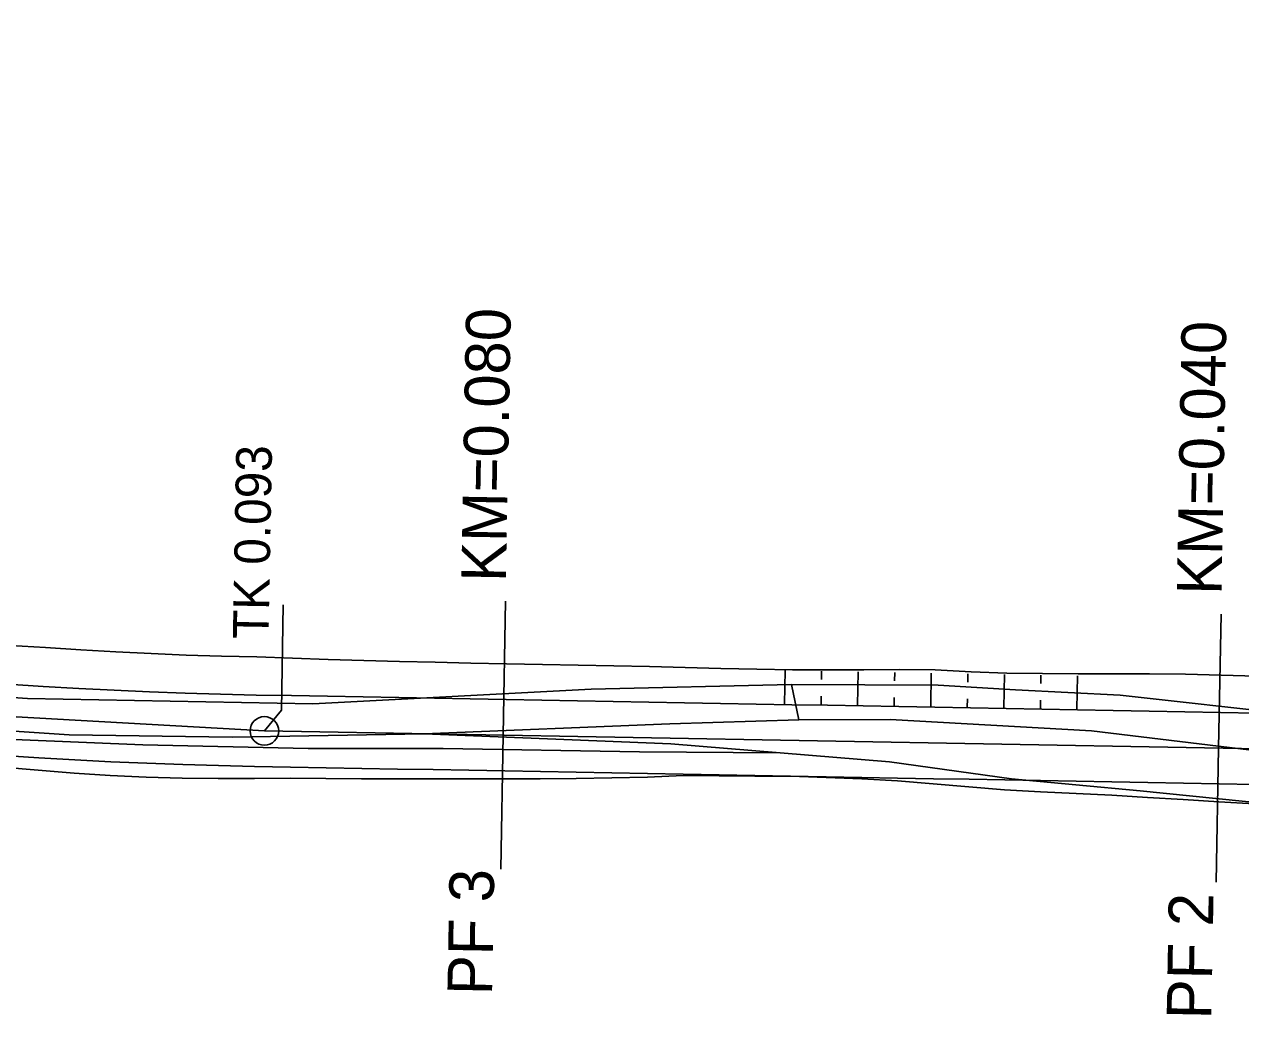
# Model space of a CAD drawing. Extents: x -478000 to -474772, y -1116940 to -1114124.
# Drawn here: x -477364.4 to -477296.3, y -1116626.8 to -1116571.3 of the extents above; entities that cross this region are included whole.
import ezdxf

# ---------------------------------------------------------------- set-up
doc = ezdxf.new("R2010")
doc.units = 0
for name, color, linetype in [('hrana_P', 7, 'Continuous'), ('L', 7, 'Continuous'), ('P', 7, 'Continuous'), ('POLYGONY_SITUACE_PF', 7, 'Continuous'), ('POLYGONY_SITUACE_PF_POPISY', 7, 'Continuous'), ('POLYGONY_SITUACE_PO', 7, 'Continuous')]:
    doc.layers.add(name, color=color, linetype=linetype)

msp = doc.modelspace()

# ---------------------------------------------------------------- linework, layer by layer
for points in [[(-477349.986, -1116609.731), (-477349.879, -1116603.837)], [(-477349.986, -1116609.731), (-477350.936, -1116610.9)]]:
    msp.add_lwpolyline(points)
at = {"layer": 'hrana_P'}
for p, q in [((-477365.605, -1116612.924), (-477363.595, -1116613.102)), ((-477363.595, -1116613.102), (-477361.582, -1116613.26)), ((-477361.582, -1116613.26), (-477359.568, -1116613.395)), ((-477359.568, -1116613.395), (-477357.552, -1116613.494)), ((-477357.552, -1116613.494), (-477355.534, -1116613.551)), ((-477355.534, -1116613.551), (-477353.516, -1116613.568)), ((-477353.516, -1116613.568), (-477351.497, -1116613.571)), ((-477351.497, -1116613.571), (-477349.492, -1116613.549)), ((-477349.492, -1116613.549), (-477347.492, -1116613.566)), ((-477347.492, -1116613.566), (-477345.492, -1116613.586)), ((-477345.492, -1116613.586), (-477343.492, -1116613.587)), ((-477343.492, -1116613.587), (-477341.491, -1116613.593)), ((-477341.491, -1116613.593), (-477339.491, -1116613.59)), ((-477339.491, -1116613.59), (-477337.491, -1116613.592)), ((-477337.491, -1116613.592), (-477335.49, -1116613.582)), ((-477335.49, -1116613.582), (-477333.49, -1116613.559)), ((-477333.49, -1116613.559), (-477331.489, -1116613.534)), ((-477331.489, -1116613.534), (-477329.488, -1116613.485)), ((-477329.488, -1116613.485), (-477327.486, -1116613.403)), ((-477327.486, -1116613.403), (-477325.486, -1116613.423)), ((-477325.486, -1116613.423), (-477323.486, -1116613.435)), ((-477323.486, -1116613.435), (-477321.485, -1116613.44)), ((-477321.485, -1116613.44), (-477319.486, -1116613.505)), ((-477319.486, -1116613.505), (-477317.487, -1116613.586)), ((-477317.487, -1116613.586), (-477315.489, -1116613.704)), ((-477315.489, -1116613.704), (-477313.492, -1116613.86)), ((-477313.492, -1116613.86), (-477311.494, -1116614.029)), ((-477311.494, -1116614.029), (-477309.497, -1116614.208)), ((-477309.497, -1116614.208), (-477307.499, -1116614.305)), ((-477307.499, -1116614.305), (-477305.5, -1116614.406)), ((-477305.5, -1116614.406), (-477303.502, -1116614.507)), ((-477303.502, -1116614.507), (-477301.504, -1116614.623)), ((-477301.504, -1116614.623), (-477299.505, -1116614.744)), ((-477299.505, -1116614.744), (-477297.507, -1116614.866)), ((-477297.507, -1116614.866), (-477295.509, -1116614.987))]:
    msp.add_line(p, q, dxfattribs=at)
for points in [[(-477365.153, -1116606.116), (-477363.184, -1116606.225)], [(-477363.184, -1116606.225), (-477361.216, -1116606.356)], [(-477361.216, -1116606.356), (-477359.247, -1116606.474)], [(-477359.247, -1116606.474), (-477357.277, -1116606.572)], [(-477357.277, -1116606.572), (-477355.306, -1116606.656)], [(-477355.306, -1116606.656), (-477353.335, -1116606.714)], [(-477353.335, -1116606.714), (-477351.363, -1116606.761)], [(-477351.363, -1116606.761), (-477349.371, -1116606.83)], [(-477349.371, -1116606.83), (-477347.372, -1116606.894)], [(-477347.372, -1116606.894), (-477345.372, -1116606.955)], [(-477345.372, -1116606.955), (-477343.373, -1116607.007)], [(-477343.373, -1116607.007), (-477341.374, -1116607.059)], [(-477341.374, -1116607.059), (-477339.374, -1116607.102)], [(-477339.374, -1116607.102), (-477337.374, -1116607.142)], [(-477337.374, -1116607.142), (-477335.375, -1116607.182)], [(-477335.375, -1116607.182), (-477333.375, -1116607.216)], [(-477333.375, -1116607.216), (-477331.375, -1116607.249)], [(-477331.375, -1116607.249), (-477329.376, -1116607.295)], [(-477329.376, -1116607.295), (-477327.377, -1116607.353)], [(-477327.377, -1116607.353), (-477325.377, -1116607.403)], [(-477325.377, -1116607.403), (-477323.378, -1116607.449)], [(-477323.378, -1116607.449), (-477321.378, -1116607.491)], [(-477321.822, -1116609.379), (-477321.788, -1116607.52)], [(-477321.378, -1116607.491), (-477319.378, -1116607.485)], [(-477319.742, -1116607.558), (-477319.75, -1116608.022)], [(-477319.378, -1116607.485), (-477317.377, -1116607.477)], [(-477317.73, -1116609.454), (-477317.696, -1116607.595)], [(-477317.377, -1116607.477), (-477315.376, -1116607.458)], [(-477315.65, -1116607.633), (-477315.658, -1116608.098)], [(-477315.376, -1116607.458), (-477313.377, -1116607.48)], [(-477313.638, -1116609.53), (-477313.603, -1116607.671)], [(-477313.377, -1116607.48), (-477311.378, -1116607.596)], [(-477311.557, -1116607.709), (-477311.566, -1116608.173)], [(-477311.378, -1116607.596), (-477309.379, -1116607.673)], [(-477309.545, -1116609.605), (-477309.511, -1116607.746)], [(-477309.379, -1116607.673), (-477307.379, -1116607.687)], [(-477307.465, -1116607.784), (-477307.474, -1116608.249)], [(-477307.379, -1116607.687), (-477305.379, -1116607.697)], [(-477305.453, -1116609.681), (-477305.419, -1116607.822)], [(-477305.379, -1116607.697), (-477303.379, -1116607.701)], [(-477303.379, -1116607.701), (-477301.379, -1116607.704)], [(-477301.379, -1116607.704), (-477299.379, -1116607.723)], [(-477299.379, -1116607.723), (-477297.379, -1116607.777)], [(-477297.379, -1116607.777), (-477295.38, -1116607.831)], [(-477363.315, -1116608.417), (-477365.297, -1116608.292)], [(-477361.331, -1116608.529), (-477363.315, -1116608.417)], [(-477359.347, -1116608.628), (-477361.331, -1116608.529)], [(-477357.362, -1116608.714), (-477359.347, -1116608.628)], [(-477355.377, -1116608.786), (-477357.362, -1116608.714)], [(-477353.391, -1116608.845), (-477355.377, -1116608.786)], [(-477351.405, -1116608.891), (-477353.391, -1116608.845)], [(-477349.409, -1116608.927), (-477351.405, -1116608.891)], [(-477347.409, -1116608.964), (-477349.409, -1116608.927)], [(-477345.409, -1116609), (-477347.409, -1116608.964)], [(-477343.41, -1116609.036), (-477345.409, -1116609)], [(-477341.41, -1116609.072), (-477343.41, -1116609.036)], [(-477339.41, -1116609.108), (-477341.41, -1116609.072)], [(-477337.41, -1116609.144), (-477339.41, -1116609.108)], [(-477335.411, -1116609.18), (-477337.41, -1116609.144)], [(-477333.411, -1116609.216), (-477335.411, -1116609.18)], [(-477331.411, -1116609.252), (-477333.411, -1116609.216)], [(-477319.776, -1116609.417), (-477319.768, -1116608.952)], [(-477315.684, -1116609.492), (-477315.675, -1116609.027)], [(-477311.592, -1116609.568), (-477311.583, -1116609.103)], [(-477307.499, -1116609.643), (-477307.491, -1116609.178)], [(-477329.412, -1116609.288), (-477331.411, -1116609.252)], [(-477327.412, -1116609.324), (-477329.412, -1116609.288)], [(-477325.412, -1116609.36), (-477327.412, -1116609.324)], [(-477323.413, -1116609.396), (-477325.412, -1116609.36)], [(-477321.413, -1116609.433), (-477323.413, -1116609.396)], [(-477319.413, -1116609.469), (-477321.413, -1116609.433)], [(-477317.414, -1116609.505), (-477319.413, -1116609.469)], [(-477315.414, -1116609.541), (-477317.414, -1116609.505)], [(-477313.414, -1116609.577), (-477315.414, -1116609.541)], [(-477311.415, -1116609.613), (-477313.414, -1116609.577)], [(-477309.415, -1116609.649), (-477311.415, -1116609.613)], [(-477307.415, -1116609.685), (-477309.415, -1116609.649)], [(-477305.416, -1116609.721), (-477307.415, -1116609.685)], [(-477303.416, -1116609.757), (-477305.416, -1116609.721)], [(-477301.416, -1116609.793), (-477303.416, -1116609.757)], [(-477299.417, -1116609.829), (-477301.416, -1116609.793)], [(-477297.417, -1116609.866), (-477299.417, -1116609.829)], [(-477295.417, -1116609.902), (-477297.417, -1116609.866)], [(-477363.553, -1116612.41), (-477365.563, -1116612.283)], [(-477361.543, -1116612.524), (-477363.553, -1116612.41)], [(-477359.532, -1116612.624), (-477361.543, -1116612.524)], [(-477357.521, -1116612.711), (-477359.532, -1116612.624)], [(-477355.509, -1116612.784), (-477357.521, -1116612.711)], [(-477353.497, -1116612.844), (-477355.509, -1116612.784)], [(-477351.484, -1116612.89), (-477353.497, -1116612.844)], [(-477349.481, -1116612.927), (-477351.484, -1116612.89)], [(-477347.481, -1116612.963), (-477349.481, -1116612.927)], [(-477345.481, -1116612.999), (-477347.481, -1116612.963)], [(-477343.482, -1116613.035), (-477345.481, -1116612.999)], [(-477341.482, -1116613.071), (-477343.482, -1116613.035)], [(-477339.482, -1116613.107), (-477341.482, -1116613.071)], [(-477337.483, -1116613.143), (-477339.482, -1116613.107)], [(-477335.483, -1116613.179), (-477337.483, -1116613.143)], [(-477333.483, -1116613.215), (-477335.483, -1116613.179)], [(-477331.484, -1116613.252), (-477333.483, -1116613.215)], [(-477329.484, -1116613.288), (-477331.484, -1116613.252)], [(-477327.484, -1116613.324), (-477329.484, -1116613.288)], [(-477325.485, -1116613.36), (-477327.484, -1116613.324)], [(-477323.485, -1116613.396), (-477325.485, -1116613.36)], [(-477321.485, -1116613.432), (-477323.485, -1116613.396)], [(-477319.486, -1116613.468), (-477321.485, -1116613.432)], [(-477317.486, -1116613.504), (-477319.486, -1116613.468)], [(-477315.486, -1116613.54), (-477317.486, -1116613.504)], [(-477313.487, -1116613.576), (-477315.486, -1116613.54)], [(-477311.487, -1116613.612), (-477313.487, -1116613.576)], [(-477309.487, -1116613.648), (-477311.487, -1116613.612)], [(-477307.488, -1116613.685), (-477309.487, -1116613.648)], [(-477305.488, -1116613.721), (-477307.488, -1116613.685)], [(-477303.488, -1116613.757), (-477305.488, -1116613.721)], [(-477301.489, -1116613.793), (-477303.488, -1116613.757)], [(-477299.489, -1116613.829), (-477301.489, -1116613.793)], [(-477297.489, -1116613.865), (-477299.489, -1116613.829)], [(-477295.489, -1116613.901), (-477297.489, -1116613.865)]]:
    msp.add_lwpolyline(points, dxfattribs=at)
at = {"layer": 'L'}
for p, q in [((-477341.992, -1116611.059), (-477328.185, -1116611.619)), ((-477328.185, -1116611.619), (-477315.937, -1116612.638)), ((-477315.937, -1116612.638), (-477309.117, -1116613.578)), ((-477309.117, -1116613.578), (-477301.915, -1116614.261)), ((-477301.915, -1116614.261), (-477293.569, -1116615.105))]:
    msp.add_line(p, q, dxfattribs=at)
for points in [[(-477415.114, -1116603.397), (-477401.483, -1116606.21), (-477390.32, -1116608.038), (-477380.629, -1116609.538), (-477373.348, -1116610.35), (-477361.864, -1116611.12), (-477352.744, -1116611.253), (-477341.992, -1116611.059), (-477328.24, -1116610.509), (-477321.01, -1116610.283), (-477315.901, -1116610.26), (-477304.626, -1116610.89), (-477295.83, -1116611.965), (-477283.629, -1116613.041), (-477275.914, -1116613.277), (-477269.979, -1116613.304), (-477265.031, -1116612.878), (-477260.374, -1116612.172), (-477255.047, -1116610.365), (-477250.042, -1116609.155), (-477245.607, -1116608.981), (-477240.155, -1116609.387), (-477231.905, -1116609.476), (-477220.847, -1116609.542)], [(-477293.304, -1116609.991), (-477303.039, -1116608.9), (-477308.895, -1116608.598), (-477313.227, -1116608.337), (-477321.433, -1116608.299), (-477332.645, -1116608.573), (-477348.219, -1116609.382), (-477364.191, -1116609.095), (-477377.001, -1116608.209)], [(-477321.01, -1116610.283), (-477321.433, -1116608.299)]]:
    msp.add_lwpolyline(points, dxfattribs=at)
at = {"layer": 'P'}
msp.add_lwpolyline([(-477434.225, -1116597.913), (-477424.384, -1116601.313), (-477415.473, -1116603.781), (-477408.364, -1116605.565), (-477400.123, -1116607.311), (-477390.915, -1116609.058), (-477382.279, -1116610.173), (-477376.508, -1116610.776), (-477368.11, -1116611.258), (-477357.738, -1116611.674), (-477348.479, -1116611.89), (-477340.931, -1116611.888), (-477329.94, -1116612.081), (-477322.061, -1116612.129)], dxfattribs=at)
at = {"layer": 'POLYGONY_SITUACE_PF'}
for points in [[(-477337.706, -1116618.64), (-477337.571, -1116611.141), (-477337.435, -1116603.643)], [(-477297.652, -1116619.363), (-477297.517, -1116611.864), (-477297.381, -1116604.365)]]:
    msp.add_lwpolyline(points, dxfattribs=at)
at = {"layer": 'POLYGONY_SITUACE_PO'}
msp.add_lwpolyline([(-477257.83, -1116608.87), (-477258.822, -1116609.197), (-477263.677, -1116610.574), (-477268.629, -1116611.538), (-477273.646, -1116612.083), (-477278.69, -1116612.204), (-477350.936, -1116610.9), (-477374.116, -1116609.583), (-477397.125, -1116606.478), (-477419.825, -1116601.602), (-477442.079, -1116594.986), (-477463.756, -1116586.668), (-477497.326, -1116572.273), (-477500.708, -1116571.338), (-477504.217, -1116571.342)], dxfattribs=at)
msp.add_circle((-477350.936, -1116610.9), 0.8, dxfattribs=at)

# ---------------------------------------------------------------- texts
msp.add_text('TK 0.093', height=2, rotation=88.96625).set_placement((-477350.703, -1116605.773))
at = {"layer": 'POLYGONY_SITUACE_PF_POPISY'}
for s, p in [('KM=0.080', (-477337.416, -1116602.574)), ('KM=0.040', (-477297.362, -1116603.297)), ('PF 3', (-477338.193, -1116625.712)), ('PF 2', (-477297.929, -1116627.065))]:
    msp.add_text(s, height=2.5, rotation=88.96625, dxfattribs=at).set_placement(p)

doc.saveas('drawing.dxf')
